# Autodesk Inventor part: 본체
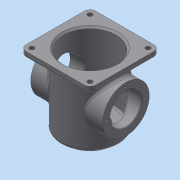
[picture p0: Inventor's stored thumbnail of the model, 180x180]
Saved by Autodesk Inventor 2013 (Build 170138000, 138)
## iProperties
Created: 2015-10
Part Number: 본체
Material: 일반
Document SubType Name: Modeling
Designer: dgall
Density: 1 g/cm^3
Author: dgall
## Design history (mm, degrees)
sketch "스케치1"
  geometry: C1 r 50 at (0, 0); 1 further point
  constraints: 1 centre point, 1 coincident
  dimensions: "d0" = 100 diameter of C1
extrude "돌출1" new body sketch "스케치1" distance "d1" = 120; taper "d2" = 0 deg
sketch "스케치2"
  geometry: L1 (-60, 60)-(60, 60); L2 (60, 60)-(60, -60); L3 (60, -60)-(-60, -60); L4 (-60, -60)-(-60, 60); C1 r 50 at (0, 0) reference; 2 further points
  constraints: 8 end point, 2 midpoint, 2 parallel, 2 perpendicular, 1 horizontal, 1 horizontal alignment, 1 vertical alignment
  dimensions: "d3" = 120 distance of L1.start L1.end
extrude "돌출2" join sketch "스케치2" distance "d5" = 10; taper "d6" = 0 deg
fillet "모깎기1" dims "d7" = 10
sketch "스케치3"
  geometry: A1 r 10 centre (50, -50) between (50, -60) and (60, -50) reference; A2 r 10 centre (50, 50) between (60, 50) and (50, 60) reference; A3 r 10 centre (-50, 50) between (-50, 60) and (-60, 50) reference; A4 r 10 centre (-50, -50) between (-60, -50) and (-50, -60) reference
hole "구멍1" sketch "스케치3" at (50, 50), (50, -50), (-50, 50), (-50, -50) diameter "d8" = 8; stored, may be unused: countersink angle "d12" = 90 deg, drill point angle "d14" = 118 deg; dims "d9" = 6, "d10" = 4, "d11" = 2, "d13" = 8
sketch "스케치4"
  geometry: C1 r 50 at (0, 0) reference; C2 r 40 at (0, 0)
  constraints: 1 centre point, 1 coincident
  dimensions: "d15" = 80 diameter of C2
extrude "돌출3" join sketch "스케치4" distance "d16" = 5; taper "d17" = 0 deg
sketch "스케치5"
  geometry: L1 (0, 0)-(0, 40); L2 (0, 0)-(22.981, 22.981); 1 further point
  constraints: 4 end point, 1 coincident, 1 vertical, 1 vertical alignment, 1 other
  dimensions: "d18" = 45 deg angle of L2 L1; "d19" = 32.5 distance of L1.start L2.end
hole "구멍2" sketch "스케치5" at (22.981, 22.981) diameter "d20" = 3.242; stored, may be unused: countersink angle "d24" = 90 deg, drill point angle "d26" = 118 deg; dims "d21" = 8, "d22" = 4, "d23" = 2, "d25" = 10
sketch "스케치7"
  geometry: C1 r 40 at (0, 0) reference; C2 r 27 at (0, 0)
  constraints: 1 centre point, 1 coincident
  dimensions: "d32" = 54 diameter of C2
extrude "돌출4" cut sketch "스케치7" distance "d33" = 13; taper "d34" = 0 deg
sketch "스케치8"
  geometry: C1 r 45 at (0, 0); 1 further point
  constraints: 1 centre point, 1 coincident
  dimensions: "d35" = 90 diameter of C1
extrude "돌출5" cut sketch "스케치8" distance "d36" = 112; taper "d37" = 0 deg
chamfer "모따기1" distance "d38" = 3; stored, may be unused: second distance "d39" = 2, angle "d40" = 45 deg
chamfer "모따기2" distance "d41" = 1; stored, may be unused: second distance "d42" = 2, angle "d43" = 45 deg
fillet "모깎기2" dims "d44" = 5
fillet "모깎기3" dims "d45" = 5
fillet "모깎기4" dims "d46" = 3
fillet "모깎기5" dims "d47" = 3
fillet "모깎기6" dims "d48" = 3
node "작업 평면1"
sketch "스케치9"
  geometry: L1 (50, 0)-(-50, 0) reference; 3 further points
  constraints: 1 midpoint, 1 vertical alignment, 1 other
  dimensions: "d49" = 70 distance from line of point (0, -70) L1
feature "엠보싱1" sketch "스케치9" dims "d50" = 0.5, "d51" = 0
node "작업 평면5"
  node "작업 평면4"
sketch "스케치12"
  geometry: C1 r 40 at (-60, 0); 1 further point
  constraints: 1 centre point, 1 horizontal alignment
  dimensions: "d65" = 80 diameter of C1; "d66" = 60 distance of point (0, 0) C1.centre
extrude "돌출8" join sketch "스케치12" stored distance "d67" = 112; taper "d68" = 0 deg
sketch "스케치13"
  geometry: C1 r 40 at (0, 0) reference; C2 r 27 at (0, 0); 1 further point
  constraints: 1 centre point, 1 coincident
  dimensions: "d69" = 54 diameter of C2
extrude "돌출9" cut sketch "스케치13" stored distance "d70" = 112; taper "d71" = 0 deg
chamfer "모따기3" distance "d72" = 1; stored, may be unused: second distance "d73" = 2, angle "d74" = 45 deg
fillet "모깎기9" dims "d75" = 3
sketch "스케치14"
  geometry: C1 r 40 at (0, 0) reference; 2 further points
  constraints: 1 vertical alignment
  dimensions: "d76" = 32.5 distance of point (0, 32.5) C1.centre
hole "구멍3" sketch "스케치14" at (0, 32.5) diameter "d77" = 3.242; stored, may be unused: countersink angle "d81" = 90 deg, drill point angle "d83" = 118 deg; dims "d78" = 8, "d79" = 4, "d80" = 2, "d82" = 10
fillet "모깎기10" dims "d87" = 5
node "솔리드1"
pattern_circular "원형 패턴1" dims angle "d28" = 360 deg
mirror "대칭2"
mirror "대칭3"
pattern_circular "원형 패턴2" dims angle "d85" = 360 deg
other parameters: "d63" = 90 deg, "d64" = 62
